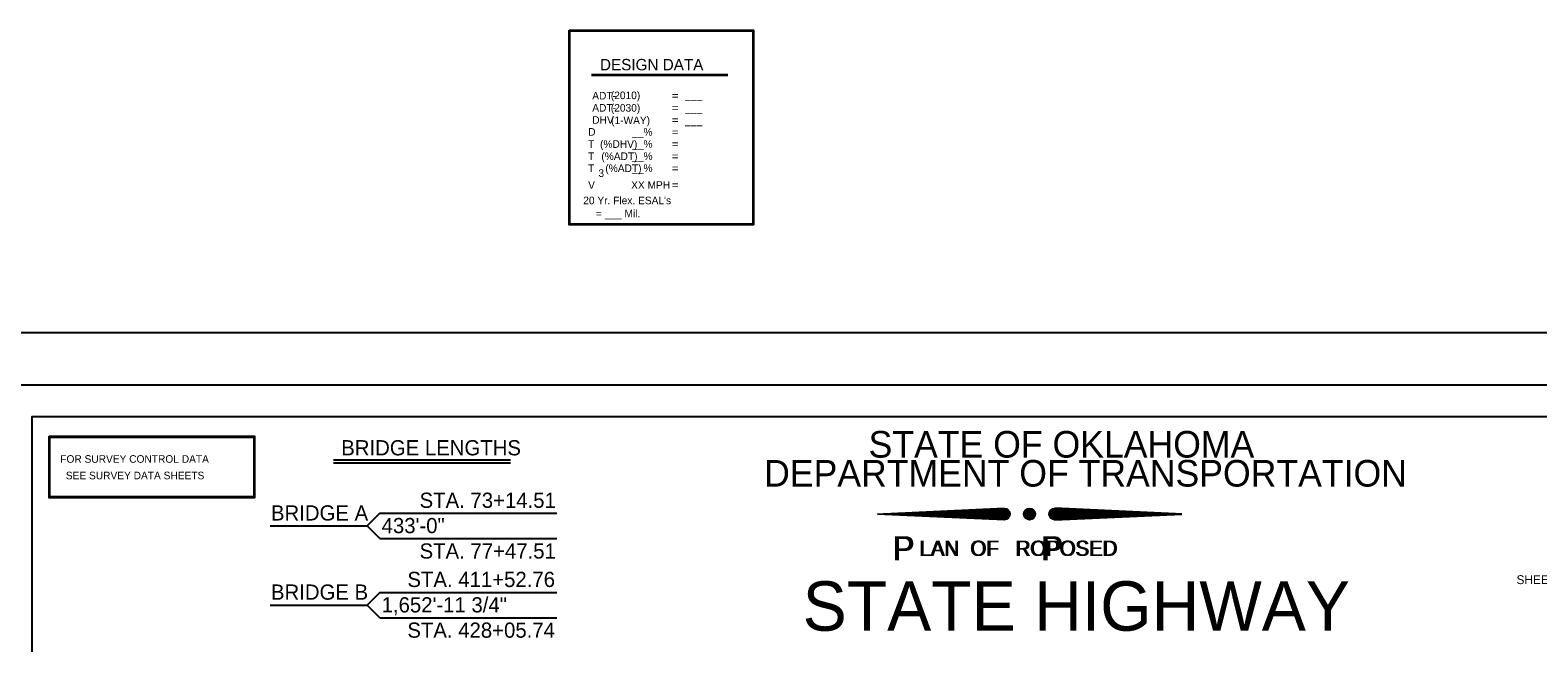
# Model space of a CAD drawing. Extents: x 2121385 to 2181200, y 132498 to 161273.
# Drawn here: x 2134915 to 2158702, y 151597 to 161273 of the extents above; entities that cross this region are included whole.
import ezdxf

# ---------------------------------------------------------------- set-up
doc = ezdxf.new("R2010")
doc.units = 0
for name, color, linetype in [('4', 7, 'Continuous'), ('SHT_Plot_Shape_Full', 7, 'Continuous'), ('SHT_Plot_Shape_Half', 7, 'Continuous'), ('SHT_Sheet_Border', 7, 'Continuous'), ('SHT_Standard_Sheet_Txt', 7, 'Continuous'), ('SHT_Title_Sheet_Design_Traffic', 7, 'Continuous'), ('SHT_Title_Sheet_Index', 7, 'Continuous')]:
    doc.layers.add(name, color=color, linetype=linetype)

msp = doc.modelspace()

# ---------------------------------------------------------------- linework, layer by layer
at = {"layer": '4'}
for p, q in [((2139702, 154489), (2142493, 154489)), ((2139702, 154439), (2142493, 154439)), ((2138703, 153443), (2140233, 153443)), ((2140433, 153643), (2140233, 153443)), ((2140433, 153243), (2140233, 153443)), ((2140433, 153643), (2143224, 153643)), ((2140433, 153243), (2143224, 153243)), ((2140433, 152393), (2140233, 152193)), ((2140433, 152393), (2143224, 152393)), ((2138703, 152193), (2140233, 152193)), ((2140433, 151993), (2140233, 152193)), ((2140433, 151993), (2143224, 151993))]:
    msp.add_line(p, q, dxfattribs=at)
at = {"layer": 'SHT_Plot_Shape_Full'}
msp.add_lwpolyline([(2131361, 156498), (2167361, 156498), (2167361, 132498), (2131361, 132498)], close=True, dxfattribs=at)
at = {"layer": 'SHT_Plot_Shape_Half'}
msp.add_lwpolyline([(2132999, 155673), (2166999, 155673), (2166999, 133673), (2132999, 133673)], close=True, dxfattribs=at)
at = {"layer": 'SHT_Sheet_Border'}
msp.add_lwpolyline([(2166449, 134173), (2134949, 134173), (2134949, 155173), (2166449, 155173)], close=True, dxfattribs=at)
at = {"layer": 'SHT_Standard_Sheet_Txt'}
for p, q in [((2148283, 153631), (2150283, 153721)), ((2148383, 153636), (2150283, 153722)), ((2148533, 153640), (2150283, 153719)), ((2148783, 153639), (2150283, 153707)), ((2149033, 153637), (2150283, 153693)), ((2149283, 153636), (2150283, 153681)), ((2149483, 153637), (2150283, 153673)), ((2149683, 153638), (2150283, 153665)), ((2150233, 153681), (2150233, 153581)), ((2150243, 153681), (2150243, 153581)), ((2150253, 153681), (2150253, 153581)), ((2150263, 153681), (2150263, 153581)), ((2150273, 153681), (2150273, 153581)), ((2150283, 153681), (2150283, 153581)), ((2150293, 153681), (2150293, 153581)), ((2150303, 153681), (2150303, 153581)), ((2150313, 153681), (2150313, 153581)), ((2150323, 153681), (2150323, 153581)), ((2150633, 153681), (2150633, 153581)), ((2150643, 153581), (2150643, 153681)), ((2150653, 153681), (2150653, 153581)), ((2150663, 153581), (2150663, 153681)), ((2150673, 153681), (2150673, 153581)), ((2150683, 153581), (2150683, 153681)), ((2150693, 153681), (2150693, 153581)), ((2150703, 153581), (2150703, 153681)), ((2150713, 153681), (2150713, 153581)), ((2150723, 153581), (2150723, 153681)), ((2151033, 153681), (2151033, 153581)), ((2151043, 153581), (2151043, 153681)), ((2151053, 153681), (2151053, 153581)), ((2151063, 153581), (2151063, 153681)), ((2151073, 153681), (2151073, 153581)), ((2152983, 153636), (2151083, 153722)), ((2153083, 153631), (2151083, 153721)), ((2152833, 153640), (2151083, 153719)), ((2152583, 153639), (2151083, 153707)), ((2152333, 153637), (2151083, 153693)), ((2152083, 153636), (2151083, 153681)), ((2151083, 153581), (2151083, 153681)), ((2151883, 153637), (2151083, 153673)), ((2151683, 153638), (2151083, 153665)), ((2151093, 153681), (2151093, 153581)), ((2151103, 153581), (2151103, 153681)), ((2151113, 153681), (2151113, 153581)), ((2151123, 153581), (2151123, 153681)), ((2150283, 153541), (2148283, 153631)), ((2150283, 153551), (2148383, 153636)), ((2150283, 153631), (2148483, 153631)), ((2150283, 153561), (2148533, 153640)), ((2148733, 153641), (2150363, 153641)), ((2150283, 153571), (2148783, 153639)), ((2150283, 153581), (2149033, 153637)), ((2150283, 153591), (2149283, 153636)), ((2150283, 153601), (2149483, 153637)), ((2150283, 153611), (2149683, 153638)), ((2149883, 153639), (2150283, 153657)), ((2150283, 153621), (2149883, 153639)), ((2151033, 153641), (2152663, 153641)), ((2151483, 153639), (2151083, 153657)), ((2151083, 153561), (2152833, 153640)), ((2151083, 153571), (2152583, 153639)), ((2151083, 153621), (2151483, 153639)), ((2151083, 153611), (2151683, 153638)), ((2151083, 153581), (2152333, 153637)), ((2151083, 153601), (2151883, 153637)), ((2151083, 153551), (2152983, 153636)), ((2151083, 153591), (2152083, 153636)), ((2151083, 153541), (2153083, 153631)), ((2151083, 153631), (2152883, 153631))]:
    msp.add_line(p, q, dxfattribs=at)
for points in [[(2135213, 154859), (2138454, 154859), (2138454, 153889), (2135213, 153889)], [(2135225, 154847), (2138442, 154847), (2138442, 153901), (2135225, 153901)]]:
    msp.add_lwpolyline(points, close=True, dxfattribs=at)
for centre, radius in [((2150283, 153631), 90), ((2150283, 153631), 80), ((2150283, 153631), 70), ((2150283, 153631), 60), ((2150283, 153631), 50), ((2150283, 153631), 40), ((2150683, 153631), 90), ((2150683, 153631), 80), ((2150683, 153631), 70), ((2150683, 153631), 60), ((2150683, 153631), 50), ((2150683, 153631), 40), ((2151083, 153631), 90), ((2151083, 153631), 80), ((2151083, 153631), 70), ((2151083, 153631), 60), ((2151083, 153631), 50), ((2151083, 153631), 40), ((2150283, 153631), 30), ((2150283, 153631), 20), ((2150683, 153631), 30), ((2150683, 153631), 20), ((2151083, 153631), 30), ((2151083, 153631), 20)]:
    msp.add_circle(centre, radius, dxfattribs=at)
at = {"layer": 'SHT_Title_Sheet_Design_Traffic'}
for p, q in [((2143773, 160573), (2145923, 160573)), ((2143773, 160561), (2145923, 160561))]:
    msp.add_line(p, q, dxfattribs=at)
for points in [[(2143417, 161273), (2146329, 161273), (2146329, 158198), (2143417, 158198)], [(2143429, 161261), (2146317, 161261), (2146317, 158210), (2143429, 158210)]]:
    msp.add_lwpolyline(points, close=True, dxfattribs=at)

# ---------------------------------------------------------------- texts
at = {"layer": '4'}
for s, p in [('BRIDGE LENGTHS', (2139823, 154558)), ('STA. 73+14.51', (2141059, 153729)), ('BRIDGE A', (2138714, 153529)), ('433\'-0"', (2140460, 153329)), ('STA. 77+47.51', (2141059, 152928)), ('STA. 411+52.76', (2140867, 152479)), ('BRIDGE B', (2138714, 152279)), ('1,652\'-11 3/4"', (2140460, 152078)), ('STA. 428+05.74', (2140866, 151678))]:
    msp.add_text(s, height=240, dxfattribs=at).set_placement(p)
at = {"layer": 'SHT_Standard_Sheet_Txt'}
for s, height, p in [('STATE OF OKLAHOMA', 420, (2148143, 154523)), ('FOR SURVEY CONTROL DATA', 120, (2135390, 154441)), ('DEPARTMENT OF TRANSPORTATION', 420, (2146495, 154065)), ('SEE SURVEY DATA SHEETS', 120, (2135478, 154180)), ('P', 380, (2148516, 152901)), ('P', 380, (2148526, 152901)), ('P', 380, (2148536, 152901)), ('LAN  OF   ROPOSED', 240, (2148938, 152971)), ('LAN  OF   ROPOSED', 240, (2148948, 152971)), ('LAN  OF   ROPOSED', 240, (2148958, 152971)), ('P', 380, (2150859, 152901)), ('P', 380, (2150869, 152901)), ('P', 380, (2150879, 152901)), ('STATE HIGHWAY', 780, (2147103, 151789))]:
    msp.add_text(s, height=height, dxfattribs=at).set_placement(p)
at = {"layer": 'SHT_Title_Sheet_Design_Traffic'}
for s, height, p in [('DESIGN DATA', 180, (2143905, 160638)), ('ADT-', 120, (2143783, 160178)), ('ADT-', 120, (2143783, 159986)), ('    (2010)', 120, (2143898, 160183)), ('    (2030)', 120, (2143898, 159986)), ('=', 120, (2145038, 160178)), ('=', 120, (2145048, 160178)), ('___', 120, (2145250, 160186)), ('DHV', 120, (2143783, 159794)), ('  (1-WAY)', 120, (2143991, 159788)), ('=', 120, (2145038, 159986)), ('=', 120, (2145038, 159794)), ('=', 120, (2145048, 159986)), ('=', 120, (2145048, 159794)), ('___', 120, (2145250, 159990)), (' D', 120, (2143674, 159606)), ('             __%%%', 120, (2143834, 159606)), ('=', 120, (2145038, 159602)), ('=', 120, (2145048, 159602)), ('___', 120, (2145250, 159791)), (' T', 120, (2143674, 159414)), ('  (%%%DHV)', 120, (2143817, 159414)), ('             __%%%', 120, (2143834, 159416)), ('=', 120, (2145038, 159414)), ('=', 120, (2145048, 159414)), (' T', 120, (2143674, 159223)), (' T', 120, (2143674, 159032)), ('  (%%%ADT)', 120, (2143838, 159222)), ('  (%%%ADT)', 120, (2143901, 159032)), ('             __%%%', 120, (2143834, 159224)), ('             __%%%', 120, (2143834, 159035)), ('=', 120, (2145038, 159221)), ('=', 120, (2145048, 159221)), ('3', 120, (2143880, 158955)), ('=', 120, (2145038, 159032)), ('=', 120, (2145048, 159032)), (' V', 120, (2143674, 158767)), ('             XX MPH', 120, (2143817, 158767)), ('=', 120, (2145038, 158767)), ('=', 120, (2145048, 158767)), ("20 Yr. Flex. ESAL's", 120, (2143641, 158523)), ('= ___ Mil.', 120, (2143841, 158318))]:
    msp.add_text(s, height=height, dxfattribs=at).set_placement(p)
at = {"layer": 'SHT_Title_Sheet_Index'}
msp.add_text('SHEET NO.', height=140, dxfattribs=at).set_placement((2158365, 152525))

doc.saveas('drawing.dxf')
